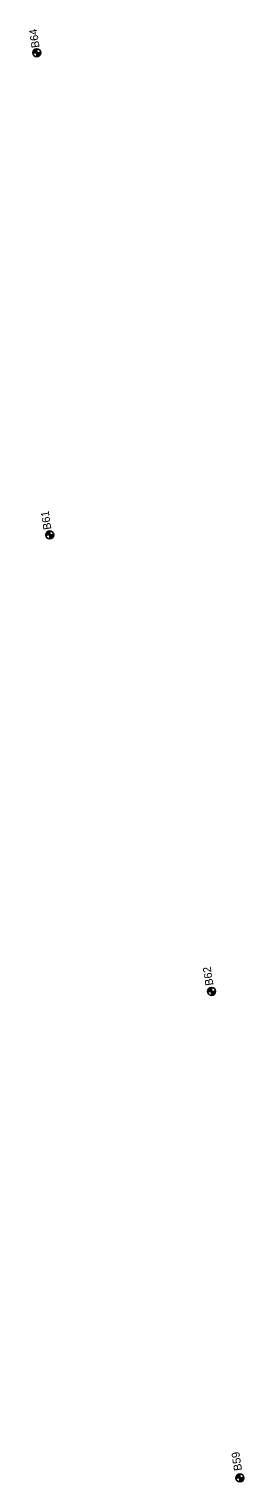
# Model space of a CAD drawing. Extents: x 331323 to 388339, y 121519 to 205315.
# Drawn here: x 359434 to 359702, y 162875 to 164690 of the extents above; entities that cross this region are included whole.
import ezdxf

# ---------------------------------------------------------------- set-up
doc = ezdxf.new("R2010")
doc.units = 0
for name, color, linetype in [('E_SOIL_BORE1 [KAPUR_CADDS_LEVELS]', 7, 'Continuous'), ('E_SOIL_BORE2 [KAPUR_CADDS_LEVELS]', 7, 'Continuous'), ('P_MARK', 7, 'Continuous')]:
    doc.layers.add(name, color=color, linetype=linetype)

msp = doc.modelspace()

# ---------------------------------------------------------------- linework, layer by layer
at = {"layer": 'P_MARK'}
for p, q in [((359438.4, 164660.9), (359448.4, 164660.9)), ((359443.4, 164665.9), (359443.4, 164655.9)), ((359454.6, 164058.3), (359464.6, 164058.3)), ((359459.6, 164063.3), (359459.6, 164053.3)), ((359661.6, 163492.9), (359661.6, 163482.9)), ((359656.6, 163487.9), (359666.6, 163487.9)), ((359692, 162879.9), (359702, 162879.9)), ((359697, 162884.9), (359697, 162874.9))]:
    msp.add_line(p, q, dxfattribs=at)
for centre in [(359443.4, 164660.9), (359459.6, 164058.3), (359661.6, 163487.9), (359697, 162879.9)]:
    msp.add_circle(centre, 5, dxfattribs=at)
for centre, radius, start, end in [((359443.4, 164660.9), 4.5, 89.9869, 179.9869), ((359443.4, 164660.9), 4, 89.9869, 179.9869), ((359443.4, 164660.9), 3.5, 89.9869, 179.9869), ((359443.4, 164660.9), 3, 89.9869, 179.9869), ((359443.4, 164660.9), 2.5, 89.9869, 179.9869), ((359443.4, 164660.9), 2, 89.9869, 179.9869), ((359443.4, 164660.9), 1.5, 89.9869, 179.9869), ((359443.4, 164660.9), 1, 89.9869, 179.9869), ((359443.4, 164660.9), 0.5, 89.9869, 179.9869), ((359443.4, 164660.9), 4.5, 269.9869, 359.9869), ((359443.4, 164660.9), 4, 269.9869, 359.9869), ((359443.4, 164660.9), 3.5, 269.9869, 359.9869), ((359443.4, 164660.9), 3, 269.9869, 359.9869), ((359443.4, 164660.9), 2.5, 269.9869, 359.9869), ((359443.4, 164660.9), 2, 269.9869, 359.9869), ((359443.4, 164660.9), 1.5, 269.9869, 359.9869), ((359443.4, 164660.9), 1, 269.9869, 359.9869), ((359443.4, 164660.9), 0.5, 269.9869, 359.9869), ((359459.6, 164058.3), 4.5, 89.9869, 179.9869), ((359459.6, 164058.3), 4, 89.9869, 179.9869), ((359459.6, 164058.3), 3.5, 89.9869, 179.9869), ((359459.6, 164058.3), 3, 89.9869, 179.9869), ((359459.6, 164058.3), 2.5, 89.9869, 179.9869), ((359459.6, 164058.3), 2, 89.9869, 179.9869), ((359459.6, 164058.3), 1.5, 89.9869, 179.9869), ((359459.6, 164058.3), 1, 89.9869, 179.9869), ((359459.6, 164058.3), 0.5, 89.9869, 179.9869), ((359459.6, 164058.3), 4.5, 269.9869, 359.9869), ((359459.6, 164058.3), 4, 269.9869, 359.9869), ((359459.6, 164058.3), 3.5, 269.9869, 359.9869), ((359459.6, 164058.3), 3, 269.9869, 359.9869), ((359459.6, 164058.3), 2.5, 269.9869, 359.9869), ((359459.6, 164058.3), 2, 269.9869, 359.9869), ((359459.6, 164058.3), 1.5, 269.9869, 359.9869), ((359459.6, 164058.3), 1, 269.9869, 359.9869), ((359459.6, 164058.3), 0.5, 269.9869, 359.9869), ((359661.6, 163487.9), 4.5, 89.9869, 179.9869), ((359661.6, 163487.9), 4, 89.9869, 179.9869), ((359661.6, 163487.9), 3.5, 89.9869, 179.9869), ((359661.6, 163487.9), 3, 89.9869, 179.9869), ((359661.6, 163487.9), 2.5, 89.9869, 179.9869), ((359661.6, 163487.9), 2, 89.9869, 179.9869), ((359661.6, 163487.9), 1.5, 89.9869, 179.9869), ((359661.6, 163487.9), 1, 89.9869, 179.9869), ((359661.6, 163487.9), 0.5, 89.9869, 179.9869), ((359661.6, 163487.9), 4.5, 269.9869, 359.9869), ((359661.6, 163487.9), 4, 269.9869, 359.9869), ((359661.6, 163487.9), 3.5, 269.9869, 359.9869), ((359661.6, 163487.9), 3, 269.9869, 359.9869), ((359661.6, 163487.9), 2.5, 269.9869, 359.9869), ((359661.6, 163487.9), 2, 269.9869, 359.9869), ((359661.6, 163487.9), 1.5, 269.9869, 359.9869), ((359661.6, 163487.9), 1, 269.9869, 359.9869), ((359661.6, 163487.9), 0.5, 269.9869, 359.9869), ((359697, 162879.9), 4.5, 89.9869, 179.9869), ((359697, 162879.9), 4, 89.9869, 179.9869), ((359697, 162879.9), 3.5, 89.9869, 179.9869), ((359697, 162879.9), 3, 89.9869, 179.9869), ((359697, 162879.9), 2.5, 89.9869, 179.9869), ((359697, 162879.9), 2, 89.9869, 179.9869), ((359697, 162879.9), 1.5, 89.9869, 179.9869), ((359697, 162879.9), 1, 89.9869, 179.9869), ((359697, 162879.9), 0.5, 89.9869, 179.9869), ((359697, 162879.9), 4.5, 269.9869, 359.9869), ((359697, 162879.9), 4, 269.9869, 359.9869), ((359697, 162879.9), 3.5, 269.9869, 359.9869), ((359697, 162879.9), 3, 269.9869, 359.9869), ((359697, 162879.9), 2.5, 269.9869, 359.9869), ((359697, 162879.9), 2, 269.9869, 359.9869), ((359697, 162879.9), 1.5, 269.9869, 359.9869), ((359697, 162879.9), 1, 269.9869, 359.9869), ((359697, 162879.9), 0.5, 269.9869, 359.9869)]:
    msp.add_arc(centre, radius, start, end, dxfattribs=at)

# ---------------------------------------------------------------- texts
at = {"layer": 'E_SOIL_BORE1 [KAPUR_CADDS_LEVELS]'}
msp.add_text('B64', height=10, rotation=98.5151, dxfattribs=at).set_placement((359447, 164667.6))
at = {"layer": 'E_SOIL_BORE2 [KAPUR_CADDS_LEVELS]'}
for s, p in [('B61', (359461.7, 164065.5)), ('B62', (359664, 163495.8)), ('B59', (359699.7, 162889.5))]:
    msp.add_text(s, height=10, rotation=98.5151, dxfattribs=at).set_placement(p)

doc.saveas('drawing.dxf')
